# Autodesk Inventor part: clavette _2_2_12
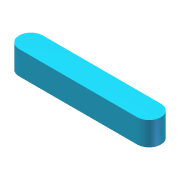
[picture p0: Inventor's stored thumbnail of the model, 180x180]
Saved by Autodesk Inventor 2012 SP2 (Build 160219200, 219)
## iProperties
Created: 2013-04
Part Number: clavette _2_2_12
Material: Default
Document SubType Name: Modeling
Designer: papa
Density: 1 g/cm^3
Mass: 0.0462832 g
Surface Area: 0.988496 cm^2
Volume: 0.0462832 cm^3
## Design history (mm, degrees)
node "clavette _2_2_121"
node "clavette _2_2_12"
node "Base1"
